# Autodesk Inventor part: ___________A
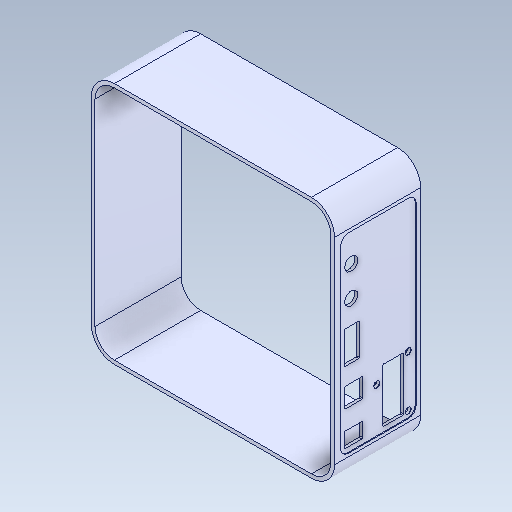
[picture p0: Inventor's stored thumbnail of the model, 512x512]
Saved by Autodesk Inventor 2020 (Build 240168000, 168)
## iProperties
Created: 2017-09
Part Number: ___________A
Material: Générique
Document SubType Name: Modeling
Designer: bruno
Density: 1 g/cm^3
Appearance: Par défaut
Author: bruno
Sending System: SolidWorks 2016
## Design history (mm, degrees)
feature "Importée1"
node "Solide1"
